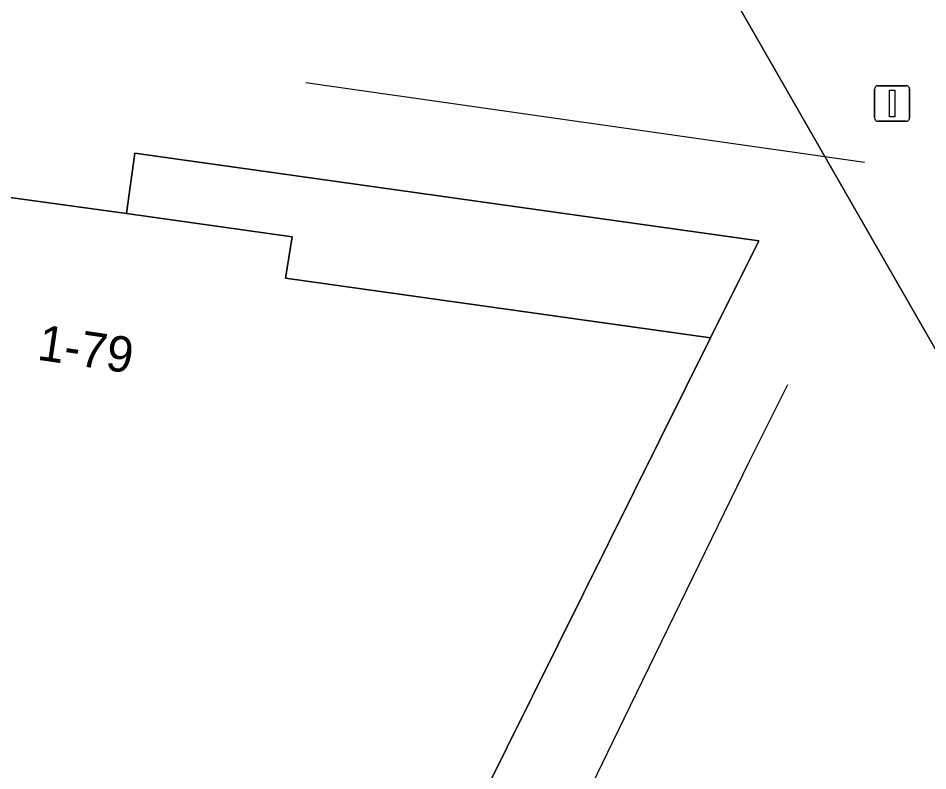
# Model space of a CAD drawing. Extents: x 155640 to 156811, y 382821 to 384049.
# Drawn here: x 156522.06 to 156547.61, y 383636.7 to 383657.83 of the extents above; entities that cross this region are included whole.
import ezdxf

# ---------------------------------------------------------------- set-up
doc = ezdxf.new("R2010")
doc.units = 0
for name, color, linetype in [('IMGEO_Lichtmast', 7, 'Continuous'), ('IMGEO_Lijnafwatering', 7, 'Continuous'), ('IMGEO_Pand', 7, 'Continuous'), ('IMGEO_Pand_nummerreeks', 7, 'Continuous'), ('IMGEO_Pand_overbouw', 7, 'Continuous'), ('IMGEO_Voetgangersgebied_open', 7, 'Continuous'), ('IMGEO_Voetpad_open', 7, 'Continuous')]:
    doc.layers.add(name, color=color, linetype=linetype)

msp = doc.modelspace()

# ---------------------------------------------------------------- linework, layer by layer
at = {"layer": 'IMGEO_Lichtmast'}
for p, q in [((156546.111, 383655.036), (156546.111, 383655.836)), ((156546.111, 383655.836), (156546.111, 383655.036)), ((156546.211, 383655.936), (156547.001, 383655.936)), ((156547.001, 383655.936), (156546.211, 383655.936)), ((156547.101, 383655.836), (156547.101, 383655.036)), ((156547.101, 383655.036), (156547.101, 383655.836)), ((156547.001, 383654.936), (156546.211, 383654.936)), ((156546.211, 383654.936), (156547.001, 383654.936))]:
    msp.add_line(p, q, dxfattribs=at)
msp.add_lwpolyline([(156546.531, 383655.811), (156546.681, 383655.811), (156546.681, 383655.061), (156546.531, 383655.061), (156546.531, 383655.811)], dxfattribs=at)
for centre, start, end in [((156546.211, 383655.836), 90, 180), ((156546.211, 383655.836), 90, 180), ((156547.001, 383655.836), 0, 90), ((156547.001, 383655.836), 360, 90), ((156546.211, 383655.036), 180, 270), ((156546.211, 383655.036), 180, 270), ((156547.001, 383655.036), 270, 0), ((156547.001, 383655.036), 270, 0)]:
    msp.add_arc(centre, 0.1, start, end, dxfattribs=at)
at = {"layer": 'IMGEO_Lijnafwatering'}
for points in [[(156545.834, 383653.783), (156530.135, 383656.021)], [(156535.401, 383630.611), (156536.183, 383632.207), (156539.082, 383638.169), (156542.6, 383645.389), (156543.681, 383647.544)]]:
    msp.add_lwpolyline(points, dxfattribs=at)
at = {"layer": 'IMGEO_Pand'}
msp.add_lwpolyline([(156515.02, 383635.654), (156517.342, 383635.331), (156517.312, 383635.113), (156533.247, 383632.905), (156533.395, 383632.884), (156533.479, 383633.068), (156533.646, 383633.045), (156541.504, 383648.852), (156529.566, 383650.531), (156529.757, 383651.696), (156525.098, 383652.346), (156520.187, 383653.02), (156520.035, 383651.904), (156458.601, 383660.428), (156423.924, 383644.238), (156430.689, 383629.765), (156454.553, 383640.906), (156454.752, 383640.999), (156459.048, 383643.004), (156459.787, 383643.35), (156463.928, 383642.773), (156464.77, 383642.655), (156509.982, 383636.356), (156510.669, 383636.26)], close=True, dxfattribs=at)
at = {"layer": 'IMGEO_Pand_overbouw'}
msp.add_lwpolyline([(156525.098, 383652.346), (156529.757, 383651.696), (156529.566, 383650.531), (156541.504, 383648.852), (156542.861, 383651.582), (156525.335, 383654.043)], close=True, dxfattribs=at)
at = {"layer": 'IMGEO_Voetgangersgebied_open'}
for points in [[(156517.613, 383674.051), (156529.811, 383667.869), (156545.356, 383678.985), (156548.717, 383677.214), (156549.16, 383669.433), (156546.554, 383662.701), (156541.778, 383659.079), (156554.507, 383636.897), (156554.548, 383637.195), (156563.438, 383701.044), (156563.835, 383703.793), (156567.525, 383730.536), (156587.015, 383727.818), (156586.969, 383727.498), (156602.082, 383725.396), (156602.618, 383725.321), (156603.279, 383719.931), (156607.846, 383719.29), (156608.586, 383724.466), (156608.705, 383724.449), (156608.932, 383724.417), (156612.599, 383751.753)], [(156518.136, 383561.224), (156527.939, 383573.822), (156530.147, 383576.636), (156532.824, 383580.075), (156549.757, 383601.973), (156553.649, 383629.149), (156553.664, 383629.256), (156553.735, 383629.771), (156554.669, 383636.496), (156554.455, 383636.526), (156554.507, 383636.897), (156541.778, 383659.079), (156532.102, 383660.765), (156530.592, 383662.499), (156529.811, 383667.869), (156517.613, 383674.051)]]:
    msp.add_lwpolyline(points, dxfattribs=at)
msp.add_lwpolyline([(156469.136, 383609.655), (156454.553, 383640.906), (156430.689, 383629.765), (156423.924, 383644.238), (156458.601, 383660.428), (156460.51, 383661.282), (156520.187, 383653.02), (156525.098, 383652.346), (156525.335, 383654.043), (156542.861, 383651.582), (156541.504, 383648.852), (156533.646, 383633.045), (156507.234, 383579.938)], close=True, dxfattribs=at)
at = {"layer": 'IMGEO_Voetpad_open'}
msp.add_lwpolyline([(156541.504, 383648.852), (156542.861, 383651.582), (156525.335, 383654.043), (156525.098, 383652.346), (156529.757, 383651.696), (156529.566, 383650.531)], close=True, dxfattribs=at)

# ---------------------------------------------------------------- texts
at = {"layer": 'IMGEO_Pand_nummerreeks'}
msp.add_text('1-79', height=1, rotation=351.5442, dxfattribs=at).set_placement((156522.564, 383648.246))

doc.saveas('drawing.dxf')
